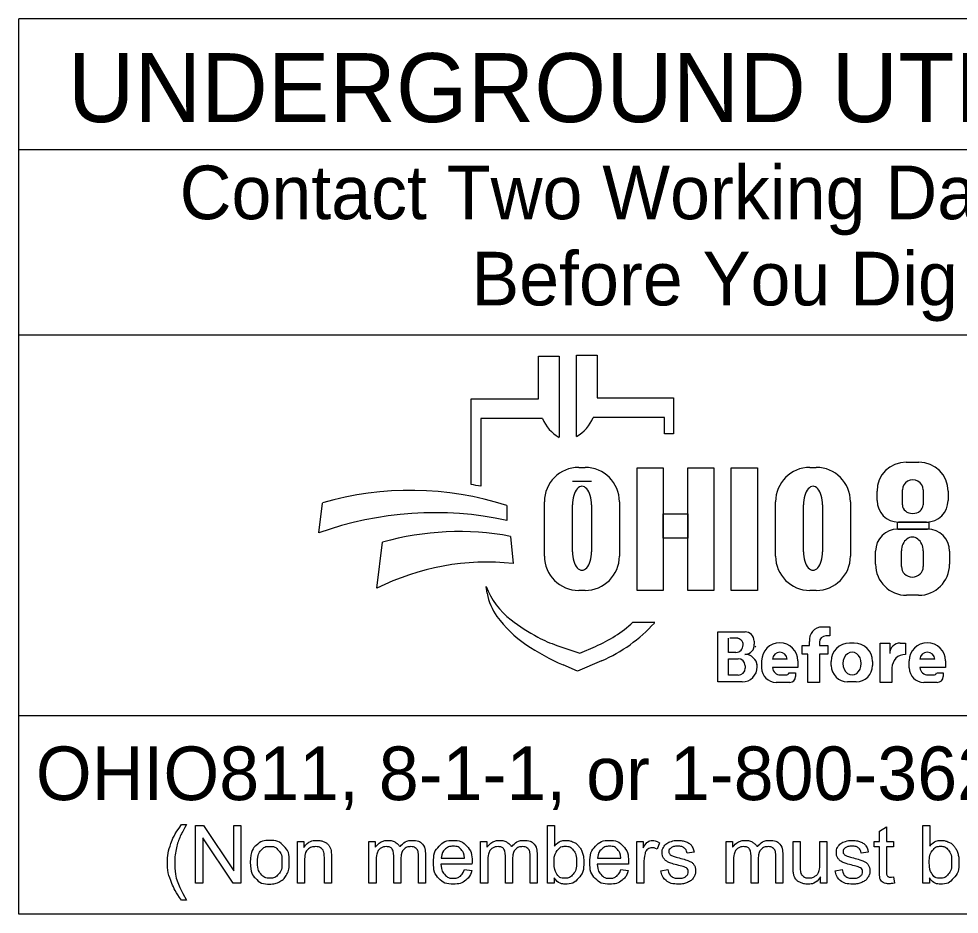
# Model space of a CAD drawing. Extents: x -38.2 to 41.9, y -4 to 24.9.
# Drawn here: x 2.378 to 4.831, y 2.143 to 4.48 of the extents above; entities that cross this region are included whole.
import ezdxf

# ---------------------------------------------------------------- set-up
doc = ezdxf.new("R2010")
doc.units = 0
doc.layers.add('SH_Data', color=7, linetype='Continuous')
doc.layers.add('SH_Text', color=7, linetype='Continuous')

msp = doc.modelspace()

# ---------------------------------------------------------------- linework, layer by layer
at = {"layer": 'SH_Data'}
for p, q in [((2.3775, 2.1428), (2.3775, 4.4803)), ((6.6275, 4.4803), (2.3775, 4.4803)), ((2.3775, 4.1387), (6.6275, 4.1387)), ((2.3775, 3.6553), (6.6275, 3.6553)), ((6.6275, 2.6607), (2.3775, 2.6607)), ((6.6275, 2.1428), (2.3775, 2.1428))]:
    msp.add_line(p, q, dxfattribs=at)
at = {"layer": 'SH_Text'}
for p, q in [((3.7335, 3.4883), (3.7335, 3.5998)), ((3.7335, 3.5998), (3.7872, 3.5998)), ((3.7872, 3.5998), (3.7872, 3.3877)), ((3.8329, 3.39), (3.8329, 3.6021)), ((3.8329, 3.6021), (3.8865, 3.6021)), ((3.8865, 3.6021), (3.8865, 3.4906)), ((3.5576, 3.2644), (3.5576, 3.4883)), ((3.5576, 3.4883), (3.7335, 3.4883)), ((3.8865, 3.4906), (4.0857, 3.4906)), ((4.0857, 3.4906), (4.0857, 3.3968)), ((3.5828, 3.4369), (3.5828, 3.26)), ((3.7439, 3.4369), (3.5828, 3.4369)), ((4.0625, 3.4392), (3.8761, 3.4392)), ((4.0625, 3.3968), (4.0625, 3.4392)), ((4.0857, 3.3968), (4.0625, 3.3968)), ((4.6931, 3.3231), (4.7258, 3.3231)), ((3.8385, 3.3091), (3.8551, 3.3091)), ((4.4416, 3.3091), (4.4581, 3.3091)), ((3.8718, 3.2721), (3.822, 3.2721)), ((4.6168, 3.2225), (4.6168, 3.2468)), ((4.683, 3.2111), (4.683, 3.2504)), ((4.7371, 3.2504), (4.7371, 3.2111)), ((4.8022, 3.2468), (4.8022, 3.2225)), ((3.1602, 3.1381), (3.1696, 3.2162)), ((3.7491, 3.0776), (3.7491, 3.2196)), ((3.9445, 3.2196), (3.9445, 3.0776)), ((4.3521, 3.0776), (4.3521, 3.2196)), ((4.5476, 3.2196), (4.5476, 3.0776)), ((3.6509, 3.2097), (3.6509, 3.1709)), ((3.822, 3.089), (3.822, 3.2114)), ((3.8718, 3.2114), (3.8718, 3.089)), ((4.425, 3.089), (4.425, 3.2114)), ((4.4748, 3.2114), (4.4748, 3.089)), ((4.7462, 3.1665), (4.6728, 3.1665)), ((4.671, 3.1482), (4.7483, 3.1482)), ((3.6608, 3.1291), (3.6671, 3.0582)), ((3.312, 2.9936), (3.3267, 3.1137)), ((4.6131, 3.0563), (4.6131, 3.0903)), ((4.6806, 3.0503), (4.6806, 3.0912)), ((4.7374, 3.0912), (4.7374, 3.0503)), ((4.8062, 3.0903), (4.8062, 3.0563)), ((3.5997, 2.9807), (3.5967, 2.9986)), ((3.8551, 2.9882), (3.8385, 2.9882)), ((4.4581, 2.9882), (4.4416, 2.9882)), ((4.7252, 2.9753), (4.6941, 2.9753)), ((3.98, 2.9048), (4.0375, 2.9048)), ((4.2013, 2.749), (4.2013, 2.8798)), ((4.2013, 2.8798), (4.2725, 2.8798)), ((4.4739, 2.8926), (4.4934, 2.8926)), ((4.4934, 2.8926), (4.4934, 2.8696)), ((4.2293, 2.8263), (4.2293, 2.8632)), ((4.2545, 2.8632), (4.2332, 2.8632)), ((4.2963, 2.856), (4.2963, 2.8481)), ((4.4406, 2.8442), (4.4406, 2.8546)), ((4.4667, 2.8526), (4.4667, 2.8442)), ((4.4934, 2.8691), (4.4832, 2.8691)), ((4.5451, 2.8508), (4.5573, 2.8508)), ((4.6254, 2.7478), (4.6254, 2.8505)), ((4.6254, 2.8505), (4.6499, 2.8505)), ((4.6499, 2.8505), (4.6499, 2.8237)), ((4.6772, 2.8505), (4.691, 2.8505)), ((4.691, 2.8505), (4.691, 2.8209)), ((3.7816, 2.8444), (3.841, 2.8239)), ((3.841, 2.8239), (3.8821, 2.8417)), ((4.2487, 2.8263), (4.2293, 2.8263)), ((4.4213, 2.8212), (4.4213, 2.8442)), ((4.4213, 2.8442), (4.4406, 2.8442)), ((4.4667, 2.8442), (4.4883, 2.8442)), ((4.4883, 2.8442), (4.4883, 2.8212)), ((3.8983, 2.8044), (3.835, 2.7769)), ((4.2293, 2.7669), (4.2293, 2.8097)), ((4.2293, 2.8097), (4.2548, 2.8097)), ((4.3159, 2.7858), (4.3159, 2.8042)), ((4.3824, 2.8082), (4.3439, 2.8082)), ((4.4104, 2.8042), (4.4104, 2.7866)), ((4.4362, 2.8212), (4.4213, 2.8212)), ((4.4362, 2.7478), (4.4362, 2.8212)), ((4.4883, 2.8212), (4.4667, 2.8212)), ((4.4667, 2.8212), (4.4667, 2.7478)), ((4.4973, 2.7922), (4.4973, 2.8029)), ((4.6051, 2.8029), (4.6051, 2.7922)), ((4.7008, 2.7858), (4.7008, 2.8042)), ((4.7674, 2.8082), (4.7288, 2.8082)), ((4.7953, 2.8042), (4.7953, 2.7866)), ((3.835, 2.7769), (3.7976, 2.7934)), ((4.2729, 2.7916), (4.2729, 2.7853)), ((4.3043, 2.7887), (4.3043, 2.7884)), ((4.4104, 2.7866), (4.344, 2.7866)), ((4.3876, 2.7729), (4.4045, 2.7729)), ((4.4045, 2.7729), (4.4045, 2.7631)), ((4.6559, 2.786), (4.6559, 2.7478)), ((4.7953, 2.7866), (4.7289, 2.7866)), ((4.7725, 2.7729), (4.7894, 2.7729)), ((4.7894, 2.7729), (4.7894, 2.7631)), ((4.265, 2.749), (4.2013, 2.749)), ((4.2546, 2.7669), (4.2293, 2.7669)), ((4.3649, 2.7673), (4.379, 2.7673)), ((4.5623, 2.7494), (4.5401, 2.7494)), ((4.7498, 2.7673), (4.7639, 2.7673)), ((4.3892, 2.7478), (4.3538, 2.7478)), ((4.4667, 2.7478), (4.4362, 2.7478)), ((4.6559, 2.7478), (4.6254, 2.7478)), ((4.7742, 2.7478), (4.7388, 2.7478))]:
    msp.add_line(p, q, dxfattribs=at)
for points in [[(3.991, 3.3081), (4.0589, 3.3081), (4.0589, 2.9881), (3.991, 2.9881)], [(4.1231, 3.3081), (4.1911, 3.3081), (4.1911, 2.9881), (4.1231, 2.9881)], [(4.2364, 3.3081), (4.3052, 3.3081), (4.3052, 2.9881), (4.2364, 2.9881)], [(4.0589, 3.1882), (4.1231, 3.1882), (4.1231, 3.1242), (4.0589, 3.1242)], [(4.6706, 3.1665), (4.7523, 3.1665), (4.7523, 3.1481), (4.6706, 3.1481)]]:
    msp.add_lwpolyline(points, close=True, dxfattribs=at)
for points in [[(2.8021, 2.3766), (2.8153, 2.3766)], [(2.8389, 2.2239), (2.8389, 2.3741), (2.8592, 2.3741), (2.9382, 2.2561), (2.9382, 2.3741), (2.9572, 2.3741), (2.9572, 2.2239), (2.9369, 2.2239), (2.8579, 2.3419), (2.8579, 2.2239), (2.8389, 2.2239)], [(3.7743, 2.2239), (3.7573, 2.2239), (3.7573, 2.3741), (3.7757, 2.3741), (3.7757, 2.3206)], [(4.6233, 2.2558), (4.6233, 2.3185), (4.6097, 2.3185), (4.6097, 2.3328), (4.6233, 2.3328), (4.6233, 2.3597), (4.6417, 2.3708), (4.6417, 2.3328), (4.6601, 2.3328), (4.6601, 2.3185), (4.6417, 2.3185), (4.6417, 2.2547)], [(4.7534, 2.2239), (4.7363, 2.2239), (4.7363, 2.3741), (4.7548, 2.3741), (4.7548, 2.3206)], [(3.1048, 2.2239), (3.1048, 2.3328), (3.1214, 2.3328), (3.1214, 2.3173)], [(3.2912, 2.2239), (3.2912, 2.3328), (3.3077, 2.3328), (3.3077, 2.3174)], [(3.5826, 2.2239), (3.5826, 2.3328), (3.5991, 2.3328), (3.5991, 2.3174)], [(3.9904, 2.2239), (3.9904, 2.3328), (4.007, 2.3328), (4.007, 2.3163)], [(4.2236, 2.2239), (4.2236, 2.3328), (4.2401, 2.3328), (4.2401, 2.3174)], [(4.3979, 2.2654), (4.3979, 2.3328), (4.4164, 2.3328), (4.4164, 2.2724)], [(4.4676, 2.2745), (4.4676, 2.3328), (4.4861, 2.3328), (4.4861, 2.2239), (4.4696, 2.2239)], [(4.0495, 2.3293), (4.043, 2.3122)], [(3.1233, 2.2833), (3.1233, 2.2239), (3.1048, 2.2239)], [(3.1932, 2.2908), (3.1932, 2.2239), (3.1748, 2.2239), (3.1748, 2.2901)], [(3.3743, 2.2871), (3.3743, 2.2239), (3.3559, 2.2239), (3.3559, 2.2946)], [(3.4388, 2.2986), (3.4388, 2.2239), (3.4203, 2.2239), (3.4203, 2.2924)], [(3.4799, 2.2887), (3.5406, 2.2887)], [(3.6657, 2.2871), (3.6657, 2.2239), (3.6473, 2.2239), (3.6473, 2.2946)], [(3.7301, 2.2986), (3.7301, 2.2239), (3.7117, 2.2239), (3.7117, 2.2924)], [(3.8879, 2.2887), (3.9486, 2.2887)], [(4.1394, 2.3046), (4.1213, 2.3022)], [(4.3067, 2.2871), (4.3067, 2.2239), (4.2883, 2.2239), (4.2883, 2.2946)], [(4.3711, 2.2986), (4.3711, 2.2239), (4.3527, 2.2239), (4.3527, 2.2924)], [(4.594, 2.3046), (4.5759, 2.3022)], [(3.3097, 2.2803), (3.3097, 2.2239), (3.2912, 2.2239)], [(3.56, 2.2736), (3.4788, 2.2736)], [(3.5404, 2.2591), (3.5595, 2.2567)], [(3.601, 2.2803), (3.601, 2.2239), (3.5826, 2.2239)], [(3.968, 2.2736), (3.8868, 2.2736)], [(3.9484, 2.2591), (3.9675, 2.2567)], [(4.0088, 2.2809), (4.0088, 2.2239), (3.9904, 2.2239)], [(4.053, 2.2564), (4.0712, 2.2593)], [(4.242, 2.2803), (4.242, 2.2239), (4.2236, 2.2239)], [(4.5076, 2.2564), (4.5258, 2.2593)], [(3.7743, 2.2375), (3.7743, 2.2239)], [(4.4696, 2.2239), (4.4696, 2.24)], [(4.6601, 2.2404), (4.6628, 2.2241)], [(4.7534, 2.2375), (4.7534, 2.2239)], [(2.8153, 2.1798), (2.8021, 2.1798)]]:
    msp.add_lwpolyline(points, dxfattribs=at)
for centre, radius, start, end in [((3.8353, 3.4736), 0.0985, 201.9296, 240.7469), ((3.7847, 3.476), 0.0985, 299.2531, 338.0704), ((4.6931, 3.2468), 0.0763, 90, 180), ((4.7258, 3.2468), 0.0763, 0, 90), ((3.8385, 3.2196), 0.0895, 90, 180), ((3.8551, 3.2196), 0.0895, 0, 90), ((4.4416, 3.2196), 0.0895, 90, 180), ((4.4581, 3.2196), 0.0895, 0, 90), ((3.4295, 2.4554), 0.8191, 79.2074, 81.0007), ((3.3997, 2.4302), 0.8191, 72.1402, 106.3144), ((4.6728, 3.2225), 0.056, 180, 270), ((4.7462, 3.2225), 0.056, 270, 0), ((3.4628, 2.2991), 0.8919, 77.8238, 109.8274), ((3.5267, 2.4094), 0.7322, 79.44, 105.8467), ((4.671, 3.0903), 0.0579, 90, 180), ((4.7483, 3.0903), 0.0579, 0, 90), ((3.8385, 3.0776), 0.0895, 180, 270), ((3.8551, 3.0776), 0.0895, 270, 0), ((4.4416, 3.0776), 0.0895, 180, 270), ((4.4581, 3.0776), 0.0895, 270, 0), ((3.5987, 2.4262), 0.6357, 83.8248, 116.8021), ((4.6941, 3.0563), 0.081, 180, 270), ((4.7252, 3.0563), 0.081, 270, 0), ((3.7841, 3.0707), 0.2008, 201.0457, 232.5314), ((3.741, 3.0048), 0.1433, 189.6817, 216.0884), ((3.8747, 3.1022), 0.3088, 216.0884, 235.7167), ((3.9766, 3.3219), 0.5173, 232.5314, 241.794), ((3.7387, 3.1722), 0.3602, 293.4582, 312.0712), ((3.7387, 3.1722), 0.401, 293.4582, 317.8286), ((4.2725, 2.856), 0.0238, 0, 90), ((4.4739, 2.859), 0.0335, 90, 187.5187), ((4.0412, 3.3465), 0.6044, 235.7167, 246.2325), ((3.8914, 3.1631), 0.3371, 241.794, 250.9821), ((4.2505, 2.8463), 0.0169, 357.8325, 90), ((4.2721, 2.8453), 0.0243, 270, 6.6529), ((4.3631, 2.8042), 0.0473, 0, 180), ((4.4832, 2.8526), 0.0165, 90, 180), ((4.5451, 2.8029), 0.0478, 90, 180), ((4.5573, 2.8029), 0.0478, 0, 90), ((4.6768, 2.8237), 0.0269, 89.2449, 180), ((4.7481, 2.8042), 0.0473, 0, 180), ((4.2487, 2.845), 0.0187, 270, 2.0582), ((4.2827, 2.8438), 0.0175, 347.4023, 0), ((4.3632, 2.8072), 0.0193, 2.9632, 177.0368), ((4.7481, 2.8072), 0.0193, 2.9632, 177.0368), ((4.2548, 2.7916), 0.0181, 0, 90), ((4.2722, 2.7889), 0.0321, 4.0748, 90), ((4.6908, 2.786), 0.0349, 89.6033, 180), ((4.2546, 2.7853), 0.0184, 270, 0), ((4.265, 2.7884), 0.0393, 270, 0), ((4.2714, 2.7887), 0.033, 0, 11.7502), ((4.3538, 2.7858), 0.038, 180, 270), ((4.3649, 2.7883), 0.021, 184.827, 270), ((4.379, 2.7767), 0.00938, 270, 335.9979), ((4.5401, 2.7922), 0.0428, 180, 270), ((4.5623, 2.7922), 0.0428, 270, 0), ((4.7388, 2.7858), 0.038, 180, 270), ((4.7498, 2.7883), 0.021, 184.827, 270), ((4.7639, 2.7767), 0.00938, 270, 335.9979), ((4.3892, 2.7631), 0.0152, 270, 0), ((4.7742, 2.7631), 0.0152, 270, 0)]:
    msp.add_arc(centre, radius, start, end, dxfattribs=at)
for centre, major_axis, ratio, start_param, end_param in [((4.71, 3.2504), (0.0271, 0), 0.969373, 0, 3.141593), ((3.8469, 3.2114), (0, 0.0484), 0.514403, 4.712389, 7.853982), ((4.4499, 3.2114), (0, 0.0484), 0.514403, 4.712389, 7.853982), ((4.71, 3.2111), (0.0271, 0), 0.818453, 3.141593, 6.283185), ((4.709, 3.0912), (0, 0.0358), 0.794529, 4.712389, 7.853982), ((3.8469, 3.089), (0, 0.0484), 0.514403, 1.570796, 4.712389), ((4.4499, 3.089), (0, 0.0484), 0.514403, 1.570796, 4.712389), ((4.709, 3.0503), (0.0284, 0), 0.959837, 3.141593, 6.283185), ((4.5517, 2.7976), (0, 0.029), 0.832186, 4.712389, 7.853982), ((4.5517, 2.7976), (0, 0.0302), 0.797287, 1.570796, 4.712389)]:
    msp.add_ellipse(centre, major_axis=major_axis, ratio=ratio, start_param=start_param, end_param=end_param, dxfattribs=at)
for points in [[(2.8021, 2.1798), (2.7869, 2.199), (2.7763, 2.2248), (2.7657, 2.2506), (2.7657, 2.2783), (2.7657, 2.3026), (2.7736, 2.325), (2.7829, 2.3509), (2.8021, 2.3766)], [(2.8153, 2.3766), (2.8029, 2.3553), (2.7989, 2.3462), (2.7927, 2.332), (2.7891, 2.3167), (2.7847, 2.2975), (2.7847, 2.2782), (2.7847, 2.2289), (2.8153, 2.1798)], [(2.9814, 2.2783), (2.9814, 2.3085), (2.9981, 2.3231), (3.0122, 2.3352), (3.0323, 2.3352), (3.0547, 2.3352), (3.069, 2.3205), (3.0832, 2.3058), (3.0832, 2.2799), (3.0832, 2.2589), (3.0769, 2.2469), (3.0706, 2.2348), (3.0586, 2.2282), (3.0466, 2.2215), (3.0323, 2.2215), (3.0095, 2.2215), (2.9954, 2.2362), (2.9814, 2.2508), (2.9814, 2.2783)], [(3.1214, 2.3173), (3.1334, 2.3352), (3.156, 2.3352), (3.1659, 2.3352), (3.1741, 2.3316), (3.1823, 2.3281), (3.1864, 2.3224), (3.1905, 2.3166), (3.1922, 2.3087), (3.1932, 2.3036), (3.1932, 2.2908)], [(3.3077, 2.3174), (3.3128, 2.3254), (3.3214, 2.3303), (3.3299, 2.3352), (3.3407, 2.3352), (3.3528, 2.3352), (3.3606, 2.3301), (3.3683, 2.3251), (3.3715, 2.3161), (3.3844, 2.3352), (3.4051, 2.3352), (3.4213, 2.3352), (3.43, 2.3262), (3.4388, 2.3172), (3.4388, 2.2986)], [(3.5595, 2.2567), (3.555, 2.24), (3.5428, 2.2307), (3.5306, 2.2215), (3.5117, 2.2215), (3.4878, 2.2215), (3.4738, 2.2362), (3.4598, 2.2509), (3.4598, 2.2774), (3.4598, 2.3049), (3.474, 2.32), (3.4881, 2.3352), (3.5106, 2.3352), (3.5324, 2.3352), (3.5463, 2.3203), (3.5601, 2.3055), (3.5601, 2.2785), (3.5601, 2.2769), (3.56, 2.2736)], [(3.5991, 2.3174), (3.6042, 2.3254), (3.6127, 2.3303), (3.6212, 2.3352), (3.6321, 2.3352), (3.6442, 2.3352), (3.6519, 2.3301), (3.6597, 2.3251), (3.6628, 2.3161), (3.6758, 2.3352), (3.6965, 2.3352), (3.7127, 2.3352), (3.7214, 2.3262), (3.7301, 2.3172), (3.7301, 2.2986)], [(3.7757, 2.3206), (3.7874, 2.3352), (3.8055, 2.3352), (3.8155, 2.3352), (3.8245, 2.3311), (3.8335, 2.3271), (3.8392, 2.3198), (3.845, 2.3124), (3.8483, 2.3021), (3.8516, 2.2918), (3.8516, 2.28), (3.8516, 2.252), (3.8378, 2.2368), (3.8239, 2.2215), (3.8046, 2.2215), (3.7853, 2.2215), (3.7743, 2.2375)], [(3.9675, 2.2567), (3.963, 2.24), (3.9508, 2.2307), (3.9386, 2.2215), (3.9196, 2.2215), (3.8958, 2.2215), (3.8818, 2.2362), (3.8678, 2.2509), (3.8678, 2.2774), (3.8678, 2.3049), (3.882, 2.32), (3.8961, 2.3352), (3.9186, 2.3352), (3.9404, 2.3352), (3.9543, 2.3203), (3.9681, 2.3055), (3.9681, 2.2785), (3.9681, 2.2769), (3.968, 2.2736)], [(4.007, 2.3163), (4.0133, 2.3278), (4.0187, 2.3315), (4.0241, 2.3352), (4.0305, 2.3352), (4.0398, 2.3352), (4.0495, 2.3293)], [(4.0712, 2.2593), (4.0727, 2.2483), (4.0798, 2.2425), (4.0868, 2.2366), (4.0995, 2.2366), (4.1122, 2.2366), (4.1184, 2.2418), (4.1245, 2.247), (4.1245, 2.254), (4.1245, 2.2602), (4.1191, 2.2638), (4.1153, 2.2663), (4.1002, 2.2701), (4.0799, 2.2752), (4.072, 2.2789), (4.0642, 2.2827), (4.0601, 2.2893), (4.0561, 2.2959), (4.0561, 2.3038), (4.0561, 2.3111), (4.0594, 2.3173), (4.0628, 2.3235), (4.0685, 2.3276), (4.0728, 2.3308), (4.0803, 2.333), (4.0877, 2.3352), (4.0962, 2.3352), (4.109, 2.3352), (4.1187, 2.3315), (4.1284, 2.3278), (4.133, 2.3215), (4.1377, 2.3152), (4.1394, 2.3046)], [(4.2401, 2.3174), (4.2452, 2.3254), (4.2537, 2.3303), (4.2622, 2.3352), (4.2731, 2.3352), (4.2852, 2.3352), (4.2929, 2.3301), (4.3007, 2.3251), (4.3038, 2.3161), (4.3168, 2.3352), (4.3375, 2.3352), (4.3537, 2.3352), (4.3624, 2.3262), (4.3711, 2.3172), (4.3711, 2.2986)], [(4.5258, 2.2593), (4.5273, 2.2483), (4.5343, 2.2425), (4.5414, 2.2366), (4.554, 2.2366), (4.5668, 2.2366), (4.5729, 2.2418), (4.5791, 2.247), (4.5791, 2.254), (4.5791, 2.2602), (4.5736, 2.2638), (4.5698, 2.2663), (4.5548, 2.2701), (4.5345, 2.2752), (4.5266, 2.2789), (4.5188, 2.2827), (4.5147, 2.2893), (4.5107, 2.2959), (4.5107, 2.3038), (4.5107, 2.3111), (4.514, 2.3173), (4.5173, 2.3235), (4.5231, 2.3276), (4.5274, 2.3308), (4.5348, 2.333), (4.5423, 2.3352), (4.5508, 2.3352), (4.5636, 2.3352), (4.5733, 2.3315), (4.583, 2.3278), (4.5876, 2.3215), (4.5922, 2.3152), (4.594, 2.3046)], [(4.7548, 2.3206), (4.7664, 2.3352), (4.7846, 2.3352), (4.7946, 2.3352), (4.8036, 2.3311), (4.8125, 2.3271), (4.8183, 2.3198), (4.8241, 2.3124), (4.8274, 2.3021), (4.8306, 2.2918), (4.8306, 2.28), (4.8306, 2.252), (4.8168, 2.2368), (4.803, 2.2215), (4.7836, 2.2215), (4.7644, 2.2215), (4.7534, 2.2375)], [(3.0003, 2.2783), (3.0003, 2.2574), (3.0094, 2.247), (3.0185, 2.2366), (3.0323, 2.2366), (3.046, 2.2366), (3.0551, 2.2471), (3.0642, 2.2575), (3.0642, 2.279), (3.0642, 2.2991), (3.0551, 2.3095), (3.0459, 2.3199), (3.0323, 2.3199), (3.0185, 2.3199), (3.0094, 2.3096), (3.0003, 2.2992), (3.0003, 2.2783)], [(3.1748, 2.2901), (3.1748, 2.3013), (3.1726, 2.3069), (3.1705, 2.3125), (3.165, 2.3158), (3.1595, 2.3191), (3.1521, 2.3191), (3.1404, 2.3191), (3.1318, 2.3117), (3.1233, 2.3042), (3.1233, 2.2833)], [(3.3559, 2.2946), (3.3559, 2.3069), (3.3514, 2.313), (3.3469, 2.3191), (3.3366, 2.3191), (3.3288, 2.3191), (3.3222, 2.315), (3.3156, 2.311), (3.3126, 2.3031), (3.3097, 2.2952), (3.3097, 2.2803)], [(3.4203, 2.2924), (3.4203, 2.3035), (3.4185, 2.3083), (3.4168, 2.3132), (3.412, 2.3162), (3.4073, 2.3191), (3.401, 2.3191), (3.3895, 2.3191), (3.3819, 2.3115), (3.3743, 2.3039), (3.3743, 2.2871)], [(3.5406, 2.2887), (3.5394, 2.3025), (3.5337, 2.3094), (3.5249, 2.3201), (3.5108, 2.3201), (3.4981, 2.3201), (3.4894, 2.3115), (3.4808, 2.303), (3.4799, 2.2887)], [(3.6473, 2.2946), (3.6473, 2.3069), (3.6428, 2.313), (3.6383, 2.3191), (3.628, 2.3191), (3.6202, 2.3191), (3.6136, 2.315), (3.607, 2.311), (3.604, 2.3031), (3.601, 2.2952), (3.601, 2.2803)], [(3.7117, 2.2924), (3.7117, 2.3035), (3.7099, 2.3083), (3.7081, 2.3132), (3.7034, 2.3162), (3.6987, 2.3191), (3.6923, 2.3191), (3.6809, 2.3191), (3.6733, 2.3115), (3.6657, 2.3039), (3.6657, 2.2871)], [(3.7741, 2.2792), (3.7741, 2.2596), (3.7794, 2.2509), (3.7881, 2.2366), (3.8029, 2.2366), (3.815, 2.2366), (3.8238, 2.2471), (3.8326, 2.2576), (3.8326, 2.2784), (3.8326, 2.2998), (3.8241, 2.3099), (3.8157, 2.3201), (3.8038, 2.3201), (3.7917, 2.3201), (3.7829, 2.3096), (3.7741, 2.299), (3.7741, 2.2792)], [(3.9486, 2.2887), (3.9474, 2.3025), (3.9417, 2.3094), (3.9328, 2.3201), (3.9188, 2.3201), (3.9061, 2.3201), (3.8974, 2.3115), (3.8888, 2.303), (3.8879, 2.2887)], [(4.043, 2.3122), (4.0363, 2.3162), (4.0295, 2.3162), (4.0235, 2.3162), (4.0187, 2.3125), (4.0139, 2.3089), (4.0119, 2.3024), (4.0088, 2.2926), (4.0088, 2.2809)], [(4.1213, 2.3022), (4.1201, 2.3106), (4.1142, 2.3153), (4.1083, 2.3201), (4.0975, 2.3201), (4.0848, 2.3201), (4.0794, 2.3159), (4.0739, 2.3116), (4.0739, 2.306), (4.0739, 2.3024), (4.0762, 2.2995), (4.0785, 2.2966), (4.0833, 2.2946), (4.086, 2.2936), (4.0996, 2.2899), (4.1192, 2.2847), (4.1269, 2.2813), (4.1347, 2.278), (4.1391, 2.2717), (4.1435, 2.2653), (4.1435, 2.2559), (4.1435, 2.2467), (4.1381, 2.2386), (4.1327, 2.2304), (4.1226, 2.226), (4.1124, 2.2215), (4.0996, 2.2215), (4.0784, 2.2215), (4.0672, 2.2303), (4.0561, 2.2391), (4.053, 2.2564)], [(4.2883, 2.2946), (4.2883, 2.3069), (4.2838, 2.313), (4.2793, 2.3191), (4.269, 2.3191), (4.2612, 2.3191), (4.2546, 2.315), (4.248, 2.311), (4.245, 2.3031), (4.242, 2.2952), (4.242, 2.2803)], [(4.3527, 2.2924), (4.3527, 2.3035), (4.3509, 2.3083), (4.3491, 2.3132), (4.3444, 2.3162), (4.3397, 2.3191), (4.3333, 2.3191), (4.3219, 2.3191), (4.3143, 2.3115), (4.3067, 2.3039), (4.3067, 2.2871)], [(4.5759, 2.3022), (4.5747, 2.3106), (4.5688, 2.3153), (4.5629, 2.3201), (4.5521, 2.3201), (4.5394, 2.3201), (4.5339, 2.3159), (4.5285, 2.3116), (4.5285, 2.306), (4.5285, 2.3024), (4.5308, 2.2995), (4.533, 2.2966), (4.5378, 2.2946), (4.5406, 2.2936), (4.5542, 2.2899), (4.5737, 2.2847), (4.5815, 2.2813), (4.5893, 2.278), (4.5937, 2.2717), (4.5981, 2.2653), (4.5981, 2.2559), (4.5981, 2.2467), (4.5927, 2.2386), (4.5873, 2.2304), (4.5772, 2.226), (4.567, 2.2215), (4.5542, 2.2215), (4.5329, 2.2215), (4.5218, 2.2303), (4.5107, 2.2391), (4.5076, 2.2564)], [(4.7532, 2.2792), (4.7532, 2.2596), (4.7585, 2.2509), (4.7672, 2.2366), (4.782, 2.2366), (4.7941, 2.2366), (4.8029, 2.2471), (4.8116, 2.2576), (4.8116, 2.2784), (4.8116, 2.2998), (4.8032, 2.3099), (4.7948, 2.3201), (4.7828, 2.3201), (4.7708, 2.3201), (4.762, 2.3096), (4.7532, 2.299), (4.7532, 2.2792)], [(3.4788, 2.2736), (3.4799, 2.2557), (3.489, 2.2462), (3.4981, 2.2366), (3.5117, 2.2366), (3.5219, 2.2366), (3.5291, 2.242), (3.5362, 2.2473), (3.5404, 2.2591)], [(3.8868, 2.2736), (3.8879, 2.2557), (3.897, 2.2462), (3.9061, 2.2366), (3.9197, 2.2366), (3.9299, 2.2366), (3.937, 2.242), (3.9442, 2.2473), (3.9484, 2.2591)], [(4.4696, 2.24), (4.4569, 2.2215), (4.4351, 2.2215), (4.4255, 2.2215), (4.4171, 2.2252), (4.4088, 2.2289), (4.4047, 2.2345), (4.4007, 2.2401), (4.3991, 2.2482), (4.3979, 2.2536), (4.3979, 2.2654)], [(4.4164, 2.2724), (4.4164, 2.258), (4.4175, 2.253), (4.4192, 2.2457), (4.4249, 2.2416), (4.4305, 2.2374), (4.4388, 2.2374), (4.4471, 2.2374), (4.4543, 2.2417), (4.4616, 2.2459), (4.4646, 2.2533), (4.4676, 2.2606), (4.4676, 2.2745)], [(4.6628, 2.2241), (4.655, 2.2224), (4.6488, 2.2224), (4.6388, 2.2224), (4.6333, 2.2256), (4.6278, 2.2288), (4.6255, 2.234), (4.6233, 2.2392), (4.6233, 2.2558)], [(4.6417, 2.2547), (4.6417, 2.2468), (4.6427, 2.2445), (4.6436, 2.2423), (4.6458, 2.2409), (4.648, 2.2396), (4.6521, 2.2396), (4.6551, 2.2396), (4.6601, 2.2404)]]:
    msp.add_open_spline(points, degree=3, dxfattribs=at)

# ---------------------------------------------------------------- texts
for s, height, p in [('UNDERGROUND UTILITIES', 0.18, (2.5057, 4.2106)), ('Contact Two Working Days', 0.14, (2.7972, 3.9571)), ('Before You Dig', 0.14, (3.5583, 3.7321)), ('OHIO811, 8-1-1, or 1-800-362-2764', 0.14, (2.422, 2.4406))]:
    msp.add_text(s, height=height, dxfattribs=at).set_placement(p)

doc.saveas('drawing.dxf')
